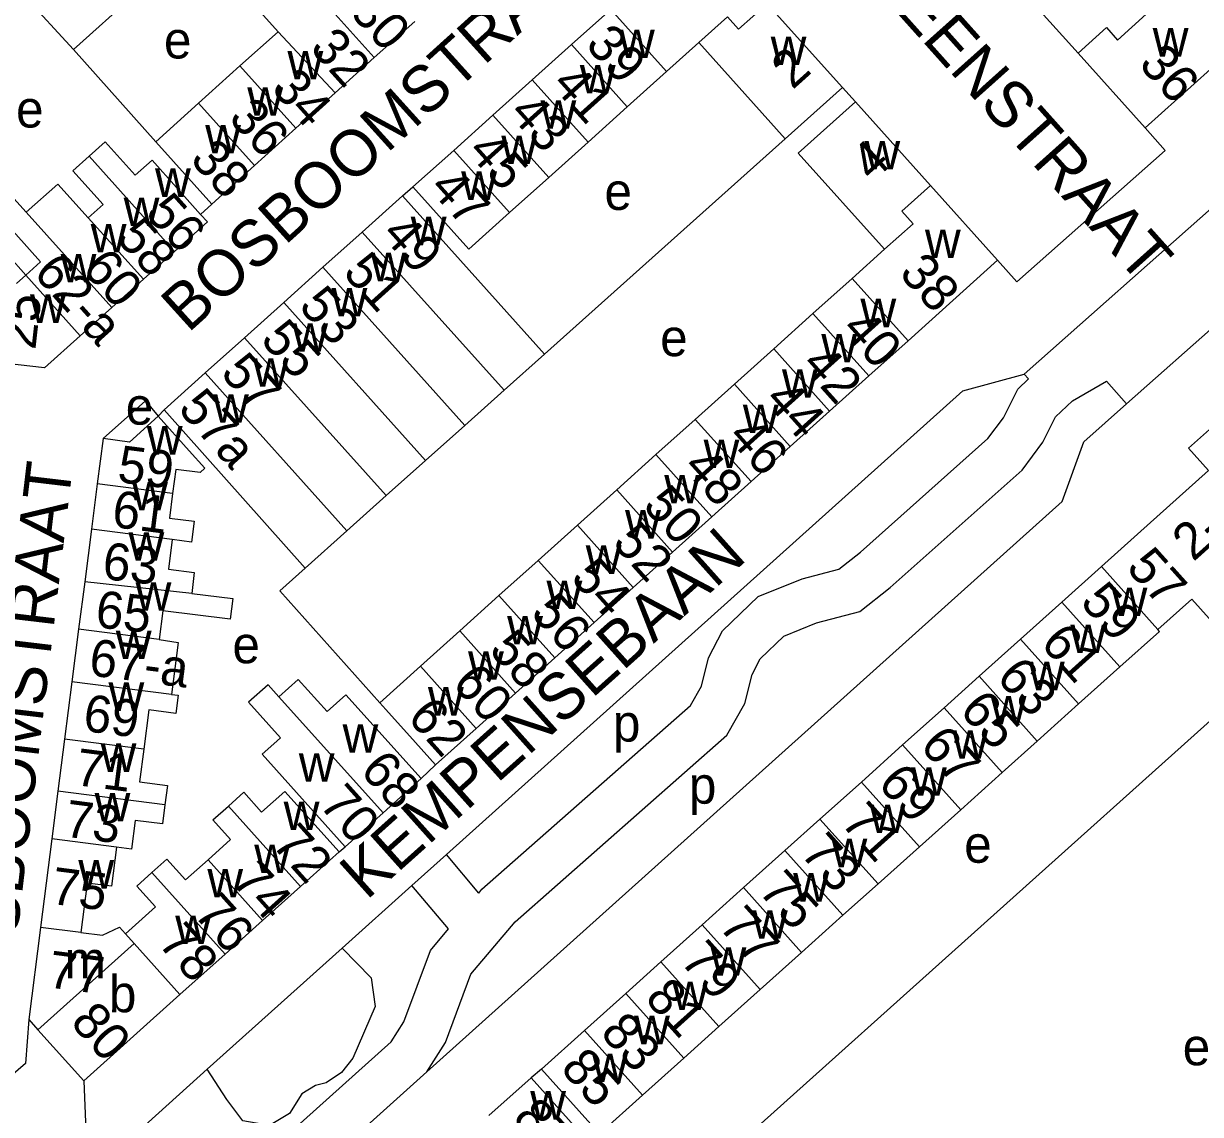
# Model space of a CAD drawing. Extents: x 161775 to 163181, y 382878 to 383925.
# Drawn here: x 162727.8 to 162855, y 383329.4 to 383447.3 of the extents above; entities that cross this region are included whole.
import ezdxf

# ---------------------------------------------------------------- set-up
doc = ezdxf.new("R2010")
doc.units = 0
for name, color, linetype in [('BLT_Basislijn', 7, 'Continuous'), ('BLT_Bebouwing', 7, 'Continuous'), ('BLT_Centroide', 7, 'Continuous'), ('BLT_Huisnummer', 7, 'Continuous'), ('BLT_Huisnummer_ tussenligend', 7, 'Continuous'), ('BLT_Huisnummer_reeks', 7, 'Continuous'), ('BLT_Onderverdeling_panden', 7, 'Continuous'), ('BLT_Straatnaam', 7, 'Continuous')]:
    doc.layers.add(name, color=color, linetype=linetype)

msp = doc.modelspace()

# ---------------------------------------------------------------- linework, layer by layer
at = {"layer": 'BLT_Basislijn'}
for p, q in [((162733.2, 383444.49), (162742.11, 383434.52)), ((162817.69, 383438.82), (162816.28, 383440.39)), ((162784.09, 383411.57), (162810.11, 383434.84)), ((162768.75, 383428.67), (162769.88, 383429.64)), ((162748.13, 383427.77), (162746.94, 383426.66)), ((162736.39, 383402.44), (162740.97, 383406.51)), ((162740.97, 383406.51), (162742.35, 383404.85)), ((162773.49, 383357.51), (162829.29, 383407.6)), ((162742.35, 383404.85), (162742.98, 383405.54)), ((162771.38, 383334.03), (162840.02, 383395.63)), ((162796.22, 383318.34), (162857.79, 383373.53)), ((162770.75, 383365.71), (162772.33, 383367.19)), ((162761.89, 383357.79), (162762.55, 383358.33)), ((162769.76, 383354.16), (162773.49, 383357.51)), ((162777, 383353.35), (162773.49, 383357.51)), ((162762.22, 383347.39), (162769.76, 383354.16)), ((162773.73, 383349.47), (162769.76, 383354.16)), ((162747.65, 383334.31), (162762.22, 383347.39)), ((162728.36, 383339.7), (162728.02, 383334.92)), ((162751.13, 383322.57), (162767.53, 383337.28)), ((162734.18, 383322.22), (162747.65, 383334.31)), ((162754.11, 383318.53), (162771.38, 383334.03)), ((162783.75, 383334.33), (162782.64, 383333.39)), ((162734.32, 383333.06), (162734.52, 383327.69))]:
    msp.add_line(p, q, dxfattribs=at)
for points in [[(162733.2, 383444.49), (162746.38, 383456.32)], [(162727.85, 383450.36), (162733.2, 383444.49)], [(162833.05, 383421.71), (162835.12, 383419.37), (162851.14, 383433.56), (162848.98, 383436)], [(162719.72, 383430.22), (162724.18, 383424.41), (162728.04, 383420.1)], [(162835.92, 383409.4), (162856.5, 383427.62)], [(162846.98, 383406.19), (162867.67, 383424.51)], [(162855.83, 383398.98), (162853.66, 383401.42), (162866.98, 383413.22), (162869.06, 383410.88)], [(162777, 383353.35), (162777.33, 383353.75), (162799.85, 383373.59), (162801.05, 383375.71), (162801.82, 383378.75), (162803.32, 383381.68), (162807.19, 383385.39), (162811.92, 383387.3), (162815.89, 383388.34), (162818.23, 383390.19), (162831.99, 383402.45), (162833.67, 383404.69), (162835.23, 383407.79), (162836.39, 383408.9), (162835.92, 383409.4)], [(162829.29, 383407.6), (162835.92, 383409.4)], [(162771.38, 383334.03), (162773.39, 383337.2), (162776.14, 383344.57), (162780.92, 383350.24), (162803.8, 383370.4), (162805.73, 383373.84), (162806.53, 383376.97), (162807.39, 383378.65), (162809.96, 383381.11), (162813.5, 383382.54), (162818.17, 383383.77), (162821.44, 383386.36), (162835.69, 383399.05), (162837.94, 383402.04), (162839.31, 383404.78), (162841.14, 383406.53), (162844.81, 383408.65), (162846.98, 383406.19)], [(162840.02, 383395.63), (162842.37, 383402.11), (162846.98, 383406.19)], [(162758.22, 383388.46), (162755.48, 383386.01), (162766.29, 383373.91)], [(162767.53, 383337.28), (162768.88, 383339.43), (162771.76, 383347.13), (162773.73, 383349.47)], [(162762.22, 383347.39), (162765.35, 383344.2), (162765.81, 383341.08), (162763.37, 383335.52), (162762.16, 383333.95), (162760.51, 383332.85), (162759.35, 383332.56), (162757.88, 383331.64), (162756.53, 383329.54), (162754.39, 383328.24), (162751.51, 383328.73), (162749.75, 383331.04), (162747.65, 383334.31)], [(162728.02, 383334.92), (162716.54, 383325.02), (162725.36, 383320.12), (162728.11, 383321.94)]]:
    msp.add_lwpolyline(points, dxfattribs=at)
at = {"layer": 'BLT_Bebouwing'}
for p, q in [((162841.74, 383444.07), (162833.61, 383453.12)), ((162791.25, 383448.81), (162787, 383445.01)), ((162816.28, 383440.39), (162808.16, 383449.43)), ((162787, 383445.01), (162782.76, 383441.2)), ((162797.29, 383442.09), (162800.78, 383445.23)), ((162800.78, 383445.23), (162810.11, 383434.84)), ((162858.65, 383444.69), (162848.98, 383436)), ((162848.98, 383436), (162841.74, 383444.07)), ((162782.76, 383441.2), (162778.52, 383437.39)), ((162793.04, 383438.28), (162797.29, 383442.09)), ((162810.11, 383434.84), (162816.28, 383440.39)), ((162817.69, 383438.82), (162811.51, 383433.28)), ((162825.81, 383429.77), (162817.69, 383438.82)), ((162778.52, 383437.39), (162774.28, 383433.58)), ((162788.8, 383434.47), (162793.04, 383438.28)), ((162769.88, 383429.64), (162774.28, 383433.58)), ((162784.56, 383430.66), (162788.8, 383434.47)), ((162811.51, 383433.28), (162820.84, 383422.89)), ((162780.32, 383426.86), (162784.56, 383430.66)), ((162775.92, 383422.91), (162769.88, 383429.64)), ((162833.05, 383421.71), (162825.81, 383429.77)), ((162764.39, 383424.76), (162768.75, 383428.67)), ((162768.75, 383428.67), (162784.09, 383411.57)), ((162780.32, 383426.86), (162775.92, 383422.91)), ((162747.67, 383425.85), (162744.1, 383422.65)), ((162760.15, 383420.95), (162764.39, 383424.76)), ((162744.1, 383422.65), (162740.75, 383419.65)), ((162820.84, 383422.89), (162817.34, 383419.75)), ((162755.91, 383417.14), (162760.15, 383420.95)), ((162823.38, 383413.02), (162833.05, 383421.71)), ((162740.75, 383419.65), (162737.33, 383416.59)), ((162817.34, 383419.75), (162813.1, 383415.94)), ((162751.67, 383413.34), (162755.91, 383417.14)), ((162737.33, 383416.59), (162733.92, 383413.54)), ((162813.1, 383415.94), (162808.86, 383412.13)), ((162747.42, 383409.53), (162751.67, 383413.34)), ((162819.14, 383409.22), (162823.38, 383413.02)), ((162808.86, 383412.13), (162804.62, 383408.33)), ((162784.09, 383411.57), (162779.73, 383407.67)), ((162742.98, 383405.54), (162747.42, 383409.53)), ((162814.9, 383405.41), (162819.14, 383409.22)), ((162804.62, 383408.33), (162800.38, 383404.52)), ((162779.73, 383407.67), (162775.48, 383403.87)), ((162758.22, 383388.46), (162742.98, 383405.54)), ((162810.65, 383401.6), (162814.9, 383405.41)), ((162800.38, 383404.52), (162796.13, 383400.71)), ((162775.48, 383403.87), (162771.23, 383400.08)), ((162736.39, 383402.44), (162735.76, 383397.54)), ((162806.41, 383397.79), (162810.65, 383401.6)), ((162796.13, 383400.71), (162791.89, 383396.9)), ((162771.23, 383400.08), (162766.98, 383396.28)), ((162855.83, 383398.98), (162848.18, 383392.12)), ((162802.17, 383393.98), (162806.41, 383397.79)), ((162735.76, 383397.54), (162735.14, 383392.66)), ((162791.89, 383396.9), (162787.65, 383393.1)), ((162766.98, 383396.28), (162762.73, 383392.48)), ((162797.93, 383390.18), (162802.17, 383393.98)), ((162735.14, 383392.66), (162734.41, 383386.98)), ((162787.65, 383393.1), (162783.41, 383389.29)), ((162762.73, 383392.48), (162758.22, 383388.46)), ((162848.18, 383392.12), (162844.27, 383388.61)), ((162793.69, 383386.37), (162797.93, 383390.18)), ((162783.41, 383389.29), (162779.17, 383385.48)), ((162844.27, 383388.61), (162839.99, 383384.77)), ((162734.41, 383386.98), (162733.75, 383381.84)), ((162789.45, 383382.56), (162793.69, 383386.37)), ((162779.17, 383385.48), (162774.93, 383381.67)), ((162839.99, 383384.77), (162835.53, 383380.77)), ((162785.21, 383378.75), (162789.45, 383382.56)), ((162733.75, 383381.84), (162733.03, 383376.18)), ((162774.93, 383381.67), (162770.68, 383377.86)), ((162835.53, 383380.77), (162831.06, 383376.76)), ((162780.96, 383374.95), (162785.21, 383378.75)), ((162733.03, 383376.18), (162732.24, 383369.98)), ((162831.06, 383376.76), (162827.26, 383373.36)), ((162770.75, 383365.71), (162762.63, 383374.76)), ((162776.72, 383371.14), (162780.96, 383374.95)), ((162827.26, 383373.36), (162822.79, 383369.35)), ((162732.24, 383369.98), (162731.52, 383364.37)), ((162822.79, 383369.35), (162818.33, 383365.34)), ((162770.75, 383365.71), (162766.65, 383362.02)), ((162818.33, 383365.34), (162813.86, 383361.34)), ((162731.52, 383364.37), (162730.85, 383359.19)), ((162766.65, 383362.02), (162762.55, 383358.33)), ((162813.86, 383361.34), (162810.06, 383357.93)), ((162730.85, 383359.19), (162729.63, 383349.64)), ((162757.72, 383354.05), (162761.89, 383357.79)), ((162810.06, 383357.93), (162805.6, 383353.93)), ((162753.63, 383350.38), (162757.72, 383354.05)), ((162805.6, 383353.93), (162801.13, 383349.92)), ((162729.63, 383349.64), (162728.36, 383339.7)), ((162749.58, 383346.74), (162753.63, 383350.38)), ((162801.13, 383349.92), (162796.66, 383345.91)), ((162744.7, 383342.37), (162749.58, 383346.74)), ((162796.66, 383345.91), (162792.87, 383342.51)), ((162792.87, 383342.51), (162788.4, 383338.5)), ((162728.36, 383339.7), (162729.36, 383338.58)), ((162788.4, 383338.5), (162783.75, 383334.33)), ((162790.02, 383327.33), (162783.75, 383334.33)), ((162782.64, 383333.39), (162778.08, 383329.31)), ((162788.22, 383327.14), (162782.64, 383333.39)), ((162794.67, 383331.51), (162790.02, 383327.33))]:
    msp.add_line(p, q, dxfattribs=at)
for points in [[(162748, 383454.57), (162755.32, 383446.39)], [(162765.7, 383443.61), (162770.08, 383447.52)], [(162755.32, 383446.39), (162751.18, 383442.7)], [(162761.46, 383439.79), (162765.7, 383443.61)], [(162751.18, 383442.7), (162746.72, 383438.68)], [(162757.23, 383435.98), (162761.46, 383439.79)], [(162746.72, 383438.68), (162742.11, 383434.52)], [(162752.77, 383431.96), (162757.23, 383435.98)], [(162734.88, 383432.94), (162736.63, 383434.5), (162739.86, 383430.9), (162741.7, 383432.53), (162744.33, 383429.57), (162746.94, 383426.66)], [(162742.11, 383434.52), (162748.13, 383427.77)], [(162734.79, 383426.29), (162736.4, 383427.73), (162733.14, 383431.37), (162734.88, 383432.94)], [(162748.13, 383427.77), (162752.77, 383431.96)], [(162728.04, 383420.1), (162729.63, 383421.54), (162723.98, 383427.84), (162725.79, 383429.46), (162728.1, 383426.89)], [(162728.1, 383426.89), (162731.5, 383429.94), (162734.79, 383426.29)], [(162746.94, 383426.66), (162747.67, 383425.85)], [(162727.05, 383419.19), (162728.04, 383420.1)], [(162733.92, 383413.54), (162730.08, 383410.09), (162723.41, 383410.85)], [(162742.35, 383404.85), (162739.26, 383402.07), (162736.39, 383402.44)], [(162747.39, 383399.24), (162745.69, 383401.13), (162742.35, 383404.85)], [(162747.39, 383399.24), (162746.88, 383398.78), (162744.24, 383399.12), (162743.91, 383396.5)], [(162743.91, 383396.5), (162743.57, 383393.86), (162746.25, 383393.52), (162745.96, 383391.27), (162743.87, 383391.54)], [(162743.87, 383391.54), (162743.46, 383388.32), (162746.24, 383387.97), (162745.99, 383385.71)], [(162745.99, 383385.71), (162750.41, 383385.17), (162750.14, 383382.92), (162742.85, 383383.82), (162742.45, 383380.73)], [(162854.03, 383385.1), (162850.36, 383381.82)], [(162857.79, 383373.53), (162856, 383375.53), (162859.67, 383378.83), (162854.03, 383385.1)], [(162846.27, 383377.77), (162850.53, 383381.62), (162850.36, 383381.82)], [(162742.45, 383380.73), (162744.52, 383380.41), (162743.8, 383374.8)], [(162770.68, 383377.86), (162766.29, 383373.91)], [(162841.8, 383373.77), (162846.27, 383377.77)], [(162762.63, 383374.76), (162760.61, 383372.95), (162757.49, 383376.43), (162755.39, 383374.55)], [(162743.8, 383374.8), (162744.51, 383374.71), (162744.26, 383372.76), (162741.34, 383373.14), (162740.79, 383368.89)], [(162755.39, 383374.55), (162754.22, 383375.84), (162752.12, 383373.95), (162755.56, 383370.12), (162754.83, 383369.47), (162753.57, 383368.34), (162762.55, 383358.33)], [(162766.29, 383373.91), (162766.95, 383373.18)], [(162837.33, 383369.76), (162841.8, 383373.77)], [(162772.33, 383367.19), (162776.72, 383371.14)], [(162833.54, 383366.36), (162837.33, 383369.76)], [(162740.79, 383368.89), (162740.34, 383365.35), (162743.34, 383364.97), (162743.07, 383362.89)], [(162770.16, 383369.61), (162772.33, 383367.19)], [(162829.07, 383362.35), (162833.54, 383366.36)], [(162749.93, 383362.74), (162751.6, 383364.23), (162753.52, 383362.09), (162756.02, 383364.33)], [(162743.07, 383362.89), (162742.81, 383360.81), (162739.87, 383361.19), (162739.47, 383358.09), (162737.83, 383358.29)], [(162747.74, 383356.95), (162750.17, 383359.12), (162748.27, 383361.24), (162749.93, 383362.74)], [(162824.6, 383358.35), (162829.07, 383362.35)], [(162737.83, 383358.29), (162737.3, 383354.1), (162734.69, 383354.43), (162734, 383349.08)], [(162820.14, 383354.34), (162824.6, 383358.35)], [(162741.68, 383355.55), (162743.3, 383357.01), (162745.31, 383354.77), (162747.74, 383356.95)], [(162738.81, 383348.94), (162742.06, 383351.85), (162740.05, 383354.1), (162741.68, 383355.55)], [(162816.34, 383350.94), (162820.14, 383354.34)], [(162811.87, 383346.93), (162816.34, 383350.94)], [(162734, 383349.08), (162736.32, 383348.78), (162738.16, 383349.67), (162738.81, 383348.94)], [(162807.41, 383342.92), (162811.87, 383346.93)], [(162802.94, 383338.92), (162807.41, 383342.92)], [(162734.32, 383333.06), (162744.7, 383342.37)], [(162729.36, 383338.58), (162734.32, 383333.06)], [(162799.14, 383335.51), (162802.94, 383338.92)], [(162794.67, 383331.51), (162799.14, 383335.51)]]:
    msp.add_lwpolyline(points, dxfattribs=at)
at = {"layer": 'BLT_Onderverdeling_panden'}
for p, q in [((162765.7, 383443.61), (162752.34, 383458.44)), ((162797.29, 383442.09), (162791.25, 383448.81)), ((162761.46, 383439.79), (162755.32, 383446.39)), ((162793.04, 383438.28), (162787, 383445.01)), ((162757.23, 383435.98), (162751.18, 383442.7)), ((162788.8, 383434.47), (162782.76, 383441.2)), ((162752.77, 383431.96), (162746.72, 383438.68)), ((162784.56, 383430.66), (162778.52, 383437.39)), ((162780.32, 383426.86), (162774.28, 383433.58)), ((162734.88, 383432.94), (162744.1, 383422.65)), ((162728.1, 383426.89), (162737.33, 383416.59)), ((162734.79, 383426.29), (162740.75, 383419.65)), ((162779.73, 383407.67), (162764.39, 383424.76)), ((162775.48, 383403.87), (162760.15, 383420.95)), ((162728.04, 383420.1), (162733.92, 383413.54)), ((162817.34, 383419.75), (162823.38, 383413.02)), ((162771.23, 383400.08), (162755.91, 383417.14)), ((162813.1, 383415.94), (162819.14, 383409.22)), ((162766.98, 383396.28), (162751.67, 383413.34)), ((162808.86, 383412.13), (162814.9, 383405.41)), ((162762.73, 383392.48), (162747.42, 383409.53)), ((162804.62, 383408.33), (162810.65, 383401.6)), ((162800.38, 383404.52), (162806.41, 383397.79)), ((162796.13, 383400.71), (162802.17, 383393.98)), ((162743.91, 383396.5), (162735.76, 383397.54)), ((162791.89, 383396.9), (162797.93, 383390.18)), ((162743.87, 383391.54), (162735.14, 383392.66)), ((162787.65, 383393.1), (162793.69, 383386.37)), ((162783.41, 383389.29), (162789.45, 383382.56)), ((162844.27, 383388.61), (162850.36, 383381.82)), ((162745.99, 383385.71), (162734.41, 383386.98)), ((162779.17, 383385.48), (162785.21, 383378.75)), ((162839.99, 383384.77), (162846.27, 383377.77)), ((162742.45, 383380.73), (162733.75, 383381.84)), ((162774.93, 383381.67), (162780.96, 383374.95)), ((162835.53, 383380.77), (162841.8, 383373.77)), ((162770.68, 383377.86), (162776.72, 383371.14)), ((162743.8, 383374.8), (162733.03, 383376.18)), ((162831.06, 383376.76), (162837.33, 383369.76)), ((162755.39, 383374.55), (162766.65, 383362.02)), ((162827.26, 383373.36), (162833.54, 383366.36)), ((162740.79, 383368.89), (162732.24, 383369.98)), ((162822.79, 383369.35), (162829.07, 383362.35)), ((162818.33, 383365.34), (162824.6, 383358.35)), ((162743.07, 383362.89), (162731.52, 383364.37)), ((162761.89, 383357.79), (162756.02, 383364.33)), ((162749.93, 383362.74), (162757.72, 383354.05)), ((162813.86, 383361.34), (162820.14, 383354.34)), ((162737.83, 383358.29), (162730.85, 383359.19)), ((162747.74, 383356.95), (162753.63, 383350.38)), ((162810.06, 383357.93), (162816.34, 383350.94)), ((162741.68, 383355.55), (162749.58, 383346.74)), ((162805.6, 383353.93), (162811.87, 383346.93)), ((162734, 383349.08), (162729.63, 383349.64)), ((162801.13, 383349.92), (162807.41, 383342.92)), ((162738.81, 383348.94), (162739.75, 383347.89)), ((162729.36, 383338.58), (162739.75, 383347.89)), ((162739.75, 383347.89), (162744.7, 383342.37)), ((162796.66, 383345.91), (162802.94, 383338.92)), ((162792.87, 383342.51), (162799.14, 383335.51)), ((162788.4, 383338.5), (162794.67, 383331.51))]:
    msp.add_line(p, q, dxfattribs=at)
for points in [[(162800.78, 383445.23), (162803.87, 383448), (162805.07, 383446.66), (162808.16, 383449.43)], [(162841.74, 383444.07), (162844.82, 383446.84), (162846.02, 383445.5), (162849.11, 383448.28)], [(162825.81, 383429.77), (162822.72, 383427), (162823.93, 383425.66), (162820.84, 383422.89)], [(162770.16, 383369.61), (162766.95, 383373.18)]]:
    msp.add_lwpolyline(points, dxfattribs=at)

# ---------------------------------------------------------------- texts
at = {"layer": 'BLT_Centroide'}
for s, p in [('e', (162742.97, 383443.51)), ('w', (162792.14, 383443.55)), ('w', (162849.81, 383443.72)), ('w', (162808.53, 383442.81)), ('w', (162756.32, 383441.24)), ('w', (162787.91, 383439.73)), ('w', (162751.98, 383437.32)), ('e', (162726.99, 383436.05)), ('w', (162783.66, 383435.92)), ('w', (162747.43, 383433.26)), ('w', (162779.42, 383432.11)), ('w', (162818.66, 383431.53)), ('w', (162742.01, 383428.56)), ('w', (162775.09, 383428.23)), ('e', (162790.57, 383427.15)), ('w', (162738.62, 383425.41)), ('w', (162735.06, 383422.56)), ('w', (162769.64, 383423.33)), ('w', (162825.2, 383421.94)), ('w', (162731.81, 383419.33)), ('w', (162765.31, 383419.45)), ('w', (162728.5, 383414.94)), ('w', (162761.08, 383415.64)), ('w', (162818.23, 383414.48)), ('w', (162756.84, 383411.84)), ('e', (162796.59, 383411.35)), ('w', (162814, 383410.67)), ('w', (162752.59, 383408.05)), ('w', (162809.75, 383406.86)), ('e', (162738.84, 383403.95)), ('w', (162748.28, 383404.16)), ('w', (162805.52, 383403.05)), ('w', (162741.12, 383400.72)), ('w', (162801.28, 383399.27)), ('w', (162739.53, 383394.69)), ('w', (162797.03, 383395.45)), ('w', (162792.8, 383391.64)), ('w', (162739.14, 383389.25)), ('w', (162788.55, 383387.83)), ('w', (162739.91, 383383.84)), ('w', (162784.31, 383384.02)), ('w', (162845.37, 383383.28)), ('w', (162780.06, 383380.2)), ('w', (162840.9, 383379.28)), ('w', (162737.77, 383378.62)), ('e', (162750.37, 383378.17)), ('w', (162775.83, 383376.39)), ('w', (162836.43, 383375.26)), ('w', (162736.98, 383373.03)), ('w', (162771.5, 383372.52)), ('w', (162832.3, 383371.56)), ('p', (162791.48, 383369.71)), ('w', (162762.27, 383368.51)), ('w', (162828.16, 383367.85)), ('w', (162736.13, 383366.44)), ('w', (162757.54, 383365.38)), ('p', (162799.69, 383363)), ('w', (162823.69, 383363.85)), ('w', (162735.48, 383361.09)), ('w', (162755.91, 383360.14)), ('w', (162819.23, 383359.84)), ('e', (162829.44, 383356.62)), ('w', (162752.73, 383355.5)), ('w', (162815.1, 383356.14)), ('w', (162733.72, 383353.83)), ('w', (162747.66, 383352.89)), ('w', (162810.96, 383352.43)), ('w', (162744.19, 383347.84)), ('w', (162806.51, 383348.42)), ('m', (162732.23, 383344.12)), ('w', (162802.04, 383344.42)), ('b', (162737.02, 383340.47)), ('w', (162797.9, 383340.71)), ('w', (162793.77, 383337.01)), ('e', (162853.05, 383334.74)), ('w', (162789.23, 383332.92)), ('w', (162782.55, 383328.88))]:
    msp.add_text(s, height=4, dxfattribs=at).set_placement(p)
at = {"layer": 'BLT_Huisnummer'}
for s, rotation, p in [('30', 312.009, (162762.93, 383448.46)), ('32', 312.0105, (162758.62, 383444.56)), ('39', 311.9198, (162788.4, 383444.93)), ('36', 311.9198, (162848.18, 383442.82)), ('2', 41.9185, (162810.89, 383440.07)), ('36', 312.0094, (162749.83, 383436.98)), ('43', 311.9198, (162780.14, 383437.52)), ('4', 41.9185, (162819.49, 383430.07)), ('47', 311.9198, (162771.52, 383429.43)), ('56', 311.8603, (162740.82, 383426.71)), ('60', 311.8543, (162734.01, 383420.71)), ('51', 311.9198, (162762.19, 383420.3)), ('38', 311.9198, (162822.29, 383420.23)), ('25', 83.5433, (162729.07, 383411.97)), ('55', 311.9198, (162753.28, 383413.05)), ('40', 311.9198, (162816.05, 383414.17)), ('57a', 311.9141, (162744.37, 383405.58)), ('44', 311.9198, (162807.74, 383406.55)), ('59', 352.7028, (162737.84, 383397.77)), ('48', 311.9198, (162798.92, 383399.27)), ('61', 352.7028, (162737.23, 383392.92)), ('52', 311.9198, (162791.31, 383391.12)), ('65', 353.7385, (162735.46, 383382.08)), ('56', 311.9198, (162782.47, 383383.51)), ('61', 311.8866, (162837.56, 383380.24)), ('60', 311.9198, (162773.99, 383375.89)), ('69', 352.7094, (162734.12, 383370.88)), ('65', 311.8866, (162828.81, 383372.99)), ('62', 311.9198, (162769.15, 383372.24)), ('68', 311.8946, (162764.04, 383366.49)), ('69', 311.8866, (162819.98, 383365.08)), ('70', 311.8918, (162759.62, 383362.84)), ('73', 352.6932, (162732.13, 383359.46)), ('72', 311.8918, (162754.51, 383358.55)), ('73', 311.8866, (162811.62, 383357.58)), ('74', 311.8933, (162750.15, 383354.56)), ('76', 311.8933, (162746.06, 383351.02)), ('77', 311.8866, (162802.8, 383349.68)), ('78', 311.8932, (162742.21, 383347.87)), ('77', 352.7142, (162730.33, 383343.17)), ('81', 311.8866, (162794.81, 383341.9)), ('80', 311.8917, (162732.74, 383339.3)), ('85', 311.8866, (162785.69, 383334.33)), ('87', 312.0034, (162780.51, 383328.93))]:
    msp.add_text(s, height=4, rotation=rotation, dxfattribs=at).set_placement(p)
at = {"layer": 'BLT_Huisnummer_ tussenligend'}
for s, rotation, p in [('34', 312.0094, (162754.44, 383440.2)), ('41', 311.9198, (162784.75, 383440.63)), ('38', 312.0094, (162745.67, 383432.53)), ('45', 311.9198, (162775.66, 383433.39)), ('58', 311.8543, (162737.66, 383424.07)), ('49', 311.9198, (162766.36, 383424.43)), ('53', 311.9198, (162757.41, 383416.67)), ('57', 311.9198, (162748.96, 383409.45)), ('42', 311.9198, (162811.73, 383410.35)), ('46', 311.9198, (162803.76, 383402.56)), ('50', 311.9198, (162794.59, 383395.11)), ('63', 353.7385, (162736.21, 383387.29)), ('54', 311.9198, (162786.8, 383387.32)), ('59', 311.8866, (162841.85, 383384.69)), ('58', 311.9198, (162777.97, 383379.52)), ('63', 311.8866, (162832.8, 383376.57)), ('67', 311.8866, (162824.53, 383369.17)), ('71', 352.6932, (162733.28, 383365.03)), ('71', 311.8866, (162815.99, 383360.89)), ('75', 352.6932, (162730.64, 383352.2)), ('75', 311.8866, (162807.09, 383353.52)), ('79', 311.8866, (162798.64, 383345.94)), ('83', 311.8866, (162789.99, 383338.18))]:
    msp.add_text(s, height=4, rotation=rotation, dxfattribs=at).set_placement(p)
at = {"layer": 'BLT_Huisnummer_reeks'}
for s, rotation, p in [('62-a', 311.8582, (162728.75, 383420.25)), ('2-4', 41.8849, (162854.19, 383389.07)), ('57', 311.8866, (162846.83, 383388.42)), ('67-a', 352.7094, (162734.75, 383376.89))]:
    msp.add_text(s, height=4, rotation=rotation, dxfattribs=at).set_placement(p)
at = {"layer": 'BLT_Straatnaam'}
for s, rotation, p in [('FRANS HALSSTRAAT', 41.8155, (162691.82, 383438.95)), ('JAN STEENSTRAAT', 311.7979, (162806.44, 383466.02)), ('BOSBOOMSTRAAT', 42.1107, (162745.58, 383413.78)), ('BOSBOOMSTRAAT', 83.2276, (162725.96, 383339.08)), ('KEMPENSEBAAN', 41.8258, (162764.86, 383352.5))]:
    msp.add_text(s, height=5, rotation=rotation, dxfattribs=at).set_placement(p)

doc.saveas('drawing.dxf')
